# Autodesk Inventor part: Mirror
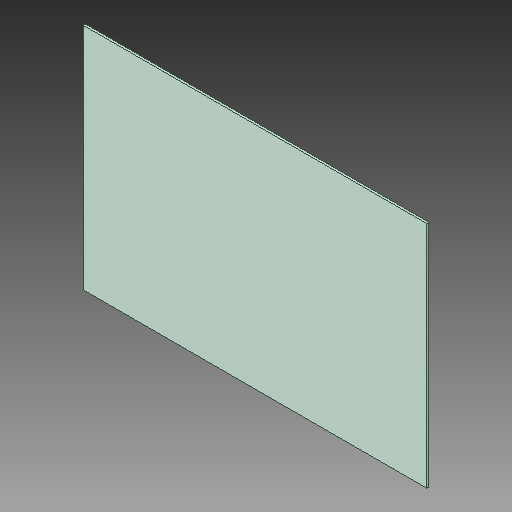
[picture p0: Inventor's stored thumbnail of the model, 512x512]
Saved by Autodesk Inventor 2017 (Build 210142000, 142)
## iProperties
Created: 2017-05
Part Number: Mirror
Material: Generic
Document SubType Name: Modeling
Designer: Savy
Density: 1 g/cm^3
Appearance: Default
Mass: 3344.51 g
Surface Area: 11331.2 cm^2
Volume: 3344.51 cm^3
Author: Savy
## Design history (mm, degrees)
feature "SOLID1"
body "Solid1"
